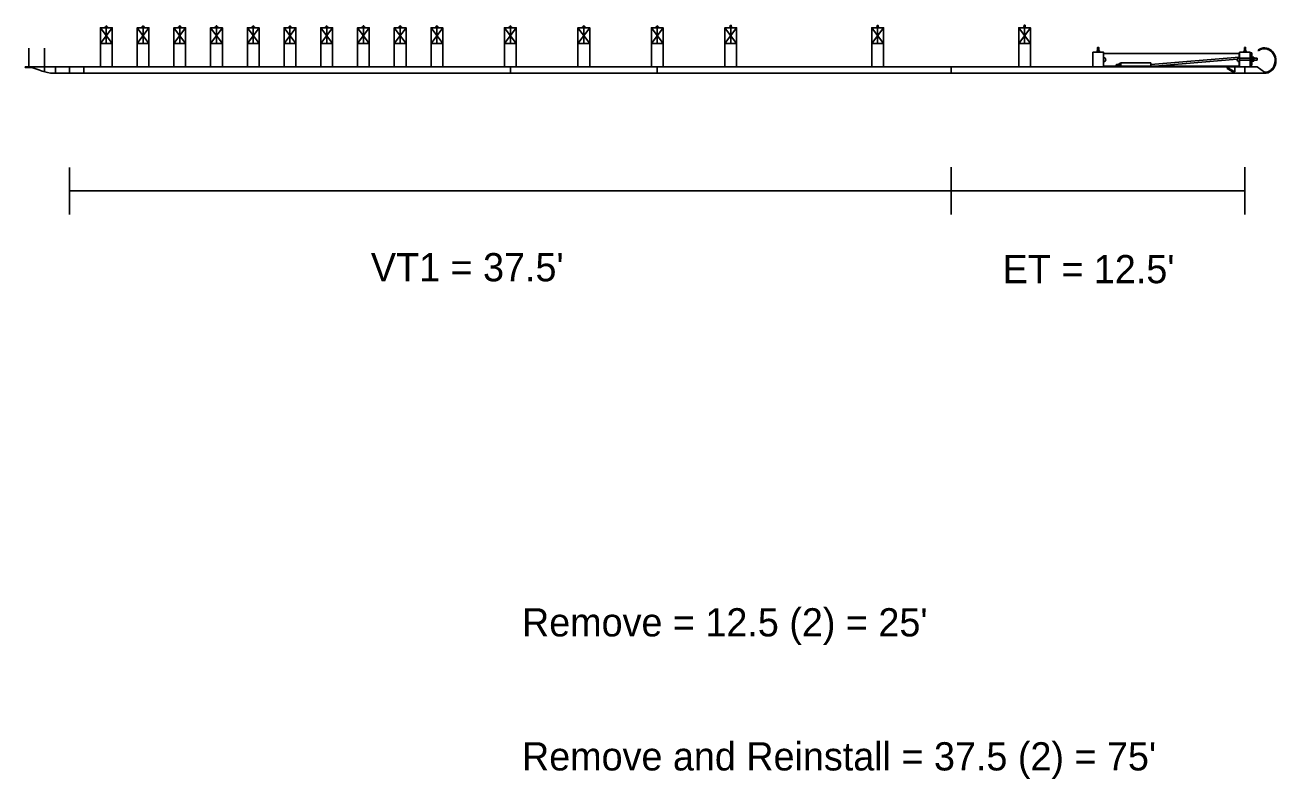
# Model space of a CAD drawing. Extents: x 16537443 to 16538473, y 7054586 to 7055469.
# Drawn here: x 16538142 to 16538195.2, y 7054852.8 to 7054884.9 of the extents above; entities that cross this region are included whole.
import ezdxf

# ---------------------------------------------------------------- set-up
doc = ezdxf.new("R2010")
doc.units = 0
doc.layers.add('Draft_DNC', color=7, linetype='Continuous')

msp = doc.modelspace()

# ---------------------------------------------------------------- linework, layer by layer
at = {"layer": 'Draft_DNC'}
for p, q in [((16538145.683, 7054884.117), (16538145.183, 7054884.784)), ((16538145.183, 7054884.117), (16538145.683, 7054884.784)), ((16538145.683, 7054884.784), (16538145.183, 7054884.784)), ((16538145.353, 7054884.784), (16538145.353, 7054884.801)), ((16538145.513, 7054884.801), (16538145.353, 7054884.801)), ((16538145.393, 7054884.801), (16538145.393, 7054884.838)), ((16538145.473, 7054884.838), (16538145.393, 7054884.838)), ((16538145.409, 7054884.801), (16538145.409, 7054884.838)), ((16538145.423, 7054884.838), (16538145.423, 7054884.867)), ((16538145.443, 7054884.867), (16538145.423, 7054884.867)), ((16538145.433, 7054884.117), (16538145.433, 7054884.784)), ((16538145.443, 7054884.838), (16538145.443, 7054884.867)), ((16538145.457, 7054884.801), (16538145.457, 7054884.838)), ((16538145.473, 7054884.801), (16538145.473, 7054884.838)), ((16538145.513, 7054884.784), (16538145.513, 7054884.801)), ((16538147.246, 7054884.117), (16538146.746, 7054884.784)), ((16538146.746, 7054884.117), (16538147.246, 7054884.784)), ((16538147.246, 7054884.784), (16538146.746, 7054884.784)), ((16538146.916, 7054884.784), (16538146.916, 7054884.801)), ((16538147.076, 7054884.801), (16538146.916, 7054884.801)), ((16538146.956, 7054884.801), (16538146.956, 7054884.838)), ((16538147.036, 7054884.838), (16538146.956, 7054884.838)), ((16538146.972, 7054884.801), (16538146.972, 7054884.838)), ((16538146.986, 7054884.838), (16538146.986, 7054884.867)), ((16538147.006, 7054884.867), (16538146.986, 7054884.867)), ((16538146.996, 7054884.117), (16538146.996, 7054884.784)), ((16538147.006, 7054884.838), (16538147.006, 7054884.867)), ((16538147.02, 7054884.801), (16538147.02, 7054884.838)), ((16538147.036, 7054884.801), (16538147.036, 7054884.838)), ((16538147.076, 7054884.784), (16538147.076, 7054884.801)), ((16538148.808, 7054884.117), (16538148.308, 7054884.784)), ((16538148.308, 7054884.117), (16538148.808, 7054884.784)), ((16538148.808, 7054884.784), (16538148.308, 7054884.784)), ((16538148.478, 7054884.784), (16538148.478, 7054884.801)), ((16538148.638, 7054884.801), (16538148.478, 7054884.801)), ((16538148.518, 7054884.801), (16538148.518, 7054884.838)), ((16538148.598, 7054884.838), (16538148.518, 7054884.838)), ((16538148.534, 7054884.801), (16538148.534, 7054884.838)), ((16538148.548, 7054884.838), (16538148.548, 7054884.867)), ((16538148.568, 7054884.867), (16538148.548, 7054884.867)), ((16538148.558, 7054884.117), (16538148.558, 7054884.784)), ((16538148.568, 7054884.838), (16538148.568, 7054884.867)), ((16538148.582, 7054884.801), (16538148.582, 7054884.838)), ((16538148.598, 7054884.801), (16538148.598, 7054884.838)), ((16538148.638, 7054884.784), (16538148.638, 7054884.801)), ((16538150.371, 7054884.117), (16538149.871, 7054884.784)), ((16538149.871, 7054884.117), (16538150.371, 7054884.784)), ((16538150.371, 7054884.784), (16538149.871, 7054884.784)), ((16538150.041, 7054884.784), (16538150.041, 7054884.801)), ((16538150.201, 7054884.801), (16538150.041, 7054884.801)), ((16538150.081, 7054884.801), (16538150.081, 7054884.838)), ((16538150.161, 7054884.838), (16538150.081, 7054884.838)), ((16538150.097, 7054884.801), (16538150.097, 7054884.838)), ((16538150.111, 7054884.838), (16538150.111, 7054884.867)), ((16538150.131, 7054884.867), (16538150.111, 7054884.867)), ((16538150.121, 7054884.117), (16538150.121, 7054884.784)), ((16538150.131, 7054884.838), (16538150.131, 7054884.867)), ((16538150.145, 7054884.801), (16538150.145, 7054884.838)), ((16538150.161, 7054884.801), (16538150.161, 7054884.838)), ((16538150.201, 7054884.784), (16538150.201, 7054884.801)), ((16538151.933, 7054884.117), (16538151.433, 7054884.784)), ((16538151.433, 7054884.117), (16538151.933, 7054884.784)), ((16538151.933, 7054884.784), (16538151.433, 7054884.784)), ((16538151.603, 7054884.784), (16538151.603, 7054884.801)), ((16538151.763, 7054884.801), (16538151.603, 7054884.801)), ((16538151.643, 7054884.801), (16538151.643, 7054884.838)), ((16538151.723, 7054884.838), (16538151.643, 7054884.838)), ((16538151.659, 7054884.801), (16538151.659, 7054884.838)), ((16538151.673, 7054884.838), (16538151.673, 7054884.867)), ((16538151.693, 7054884.867), (16538151.673, 7054884.867)), ((16538151.683, 7054884.117), (16538151.683, 7054884.784)), ((16538151.693, 7054884.838), (16538151.693, 7054884.867)), ((16538151.707, 7054884.801), (16538151.707, 7054884.838)), ((16538151.723, 7054884.801), (16538151.723, 7054884.838)), ((16538151.763, 7054884.784), (16538151.763, 7054884.801)), ((16538153.496, 7054884.117), (16538152.996, 7054884.784)), ((16538152.996, 7054884.117), (16538153.496, 7054884.784)), ((16538153.496, 7054884.784), (16538152.996, 7054884.784)), ((16538153.166, 7054884.784), (16538153.166, 7054884.801)), ((16538153.326, 7054884.801), (16538153.166, 7054884.801)), ((16538153.206, 7054884.801), (16538153.206, 7054884.838)), ((16538153.286, 7054884.838), (16538153.206, 7054884.838)), ((16538153.222, 7054884.801), (16538153.222, 7054884.838)), ((16538153.236, 7054884.838), (16538153.236, 7054884.867)), ((16538153.256, 7054884.867), (16538153.236, 7054884.867)), ((16538153.246, 7054884.117), (16538153.246, 7054884.784)), ((16538153.256, 7054884.838), (16538153.256, 7054884.867)), ((16538153.27, 7054884.801), (16538153.27, 7054884.838)), ((16538153.286, 7054884.801), (16538153.286, 7054884.838)), ((16538153.326, 7054884.784), (16538153.326, 7054884.801)), ((16538155.058, 7054884.117), (16538154.558, 7054884.784)), ((16538154.558, 7054884.117), (16538155.058, 7054884.784)), ((16538155.058, 7054884.784), (16538154.558, 7054884.784)), ((16538154.728, 7054884.784), (16538154.728, 7054884.801)), ((16538154.888, 7054884.801), (16538154.728, 7054884.801)), ((16538154.768, 7054884.801), (16538154.768, 7054884.838)), ((16538154.848, 7054884.838), (16538154.768, 7054884.838)), ((16538154.784, 7054884.801), (16538154.784, 7054884.838)), ((16538154.798, 7054884.838), (16538154.798, 7054884.867)), ((16538154.818, 7054884.867), (16538154.798, 7054884.867)), ((16538154.808, 7054884.117), (16538154.808, 7054884.784)), ((16538154.818, 7054884.838), (16538154.818, 7054884.867)), ((16538154.832, 7054884.801), (16538154.832, 7054884.838)), ((16538154.848, 7054884.801), (16538154.848, 7054884.838)), ((16538154.888, 7054884.784), (16538154.888, 7054884.801)), ((16538156.621, 7054884.117), (16538156.121, 7054884.784)), ((16538156.121, 7054884.117), (16538156.621, 7054884.784)), ((16538156.621, 7054884.784), (16538156.121, 7054884.784)), ((16538156.291, 7054884.784), (16538156.291, 7054884.801)), ((16538156.451, 7054884.801), (16538156.291, 7054884.801)), ((16538156.331, 7054884.801), (16538156.331, 7054884.838)), ((16538156.411, 7054884.838), (16538156.331, 7054884.838)), ((16538156.347, 7054884.801), (16538156.347, 7054884.838)), ((16538156.361, 7054884.838), (16538156.361, 7054884.867)), ((16538156.381, 7054884.867), (16538156.361, 7054884.867)), ((16538156.371, 7054884.117), (16538156.371, 7054884.784)), ((16538156.381, 7054884.838), (16538156.381, 7054884.867)), ((16538156.395, 7054884.801), (16538156.395, 7054884.838)), ((16538156.411, 7054884.801), (16538156.411, 7054884.838)), ((16538156.451, 7054884.784), (16538156.451, 7054884.801)), ((16538158.183, 7054884.117), (16538157.683, 7054884.784)), ((16538157.683, 7054884.117), (16538158.183, 7054884.784)), ((16538158.183, 7054884.784), (16538157.683, 7054884.784)), ((16538157.853, 7054884.784), (16538157.853, 7054884.801)), ((16538158.013, 7054884.801), (16538157.853, 7054884.801)), ((16538157.893, 7054884.801), (16538157.893, 7054884.838)), ((16538157.973, 7054884.838), (16538157.893, 7054884.838)), ((16538157.909, 7054884.801), (16538157.909, 7054884.838)), ((16538157.923, 7054884.838), (16538157.923, 7054884.867)), ((16538157.943, 7054884.867), (16538157.923, 7054884.867)), ((16538157.933, 7054884.117), (16538157.933, 7054884.784)), ((16538157.943, 7054884.838), (16538157.943, 7054884.867)), ((16538157.957, 7054884.801), (16538157.957, 7054884.838)), ((16538157.973, 7054884.801), (16538157.973, 7054884.838)), ((16538158.013, 7054884.784), (16538158.013, 7054884.801)), ((16538159.746, 7054884.117), (16538159.246, 7054884.784)), ((16538159.246, 7054884.117), (16538159.746, 7054884.784)), ((16538159.746, 7054884.784), (16538159.246, 7054884.784)), ((16538159.416, 7054884.784), (16538159.416, 7054884.801)), ((16538159.576, 7054884.801), (16538159.416, 7054884.801)), ((16538159.456, 7054884.801), (16538159.456, 7054884.838)), ((16538159.536, 7054884.838), (16538159.456, 7054884.838)), ((16538159.472, 7054884.801), (16538159.472, 7054884.838)), ((16538159.486, 7054884.838), (16538159.486, 7054884.867)), ((16538159.506, 7054884.867), (16538159.486, 7054884.867)), ((16538159.496, 7054884.117), (16538159.496, 7054884.784)), ((16538159.506, 7054884.838), (16538159.506, 7054884.867)), ((16538159.52, 7054884.801), (16538159.52, 7054884.838)), ((16538159.536, 7054884.801), (16538159.536, 7054884.838)), ((16538159.576, 7054884.784), (16538159.576, 7054884.801)), ((16538162.871, 7054884.117), (16538162.371, 7054884.784)), ((16538162.371, 7054884.117), (16538162.871, 7054884.784)), ((16538162.871, 7054884.784), (16538162.371, 7054884.784)), ((16538162.541, 7054884.784), (16538162.541, 7054884.801)), ((16538162.701, 7054884.801), (16538162.541, 7054884.801)), ((16538162.581, 7054884.801), (16538162.581, 7054884.838)), ((16538162.661, 7054884.838), (16538162.581, 7054884.838)), ((16538162.597, 7054884.801), (16538162.597, 7054884.838)), ((16538162.611, 7054884.838), (16538162.611, 7054884.867)), ((16538162.631, 7054884.867), (16538162.611, 7054884.867)), ((16538162.621, 7054884.117), (16538162.621, 7054884.784)), ((16538162.631, 7054884.838), (16538162.631, 7054884.867)), ((16538162.645, 7054884.801), (16538162.645, 7054884.838)), ((16538162.661, 7054884.801), (16538162.661, 7054884.838)), ((16538162.701, 7054884.784), (16538162.701, 7054884.801)), ((16538165.996, 7054884.117), (16538165.496, 7054884.784)), ((16538165.496, 7054884.117), (16538165.996, 7054884.784)), ((16538165.996, 7054884.784), (16538165.496, 7054884.784)), ((16538165.666, 7054884.784), (16538165.666, 7054884.801)), ((16538165.826, 7054884.801), (16538165.666, 7054884.801)), ((16538165.706, 7054884.801), (16538165.706, 7054884.838)), ((16538165.786, 7054884.838), (16538165.706, 7054884.838)), ((16538165.722, 7054884.801), (16538165.722, 7054884.838)), ((16538165.736, 7054884.838), (16538165.736, 7054884.867)), ((16538165.756, 7054884.867), (16538165.736, 7054884.867)), ((16538165.746, 7054884.117), (16538165.746, 7054884.784)), ((16538165.756, 7054884.838), (16538165.756, 7054884.867)), ((16538165.77, 7054884.801), (16538165.77, 7054884.838)), ((16538165.786, 7054884.801), (16538165.786, 7054884.838)), ((16538165.826, 7054884.784), (16538165.826, 7054884.801)), ((16538169.121, 7054884.117), (16538168.621, 7054884.784)), ((16538168.621, 7054884.117), (16538169.121, 7054884.784)), ((16538169.121, 7054884.784), (16538168.621, 7054884.784)), ((16538168.791, 7054884.784), (16538168.791, 7054884.801)), ((16538168.951, 7054884.801), (16538168.791, 7054884.801)), ((16538168.831, 7054884.801), (16538168.831, 7054884.838)), ((16538168.911, 7054884.838), (16538168.831, 7054884.838)), ((16538168.847, 7054884.801), (16538168.847, 7054884.838)), ((16538168.861, 7054884.838), (16538168.861, 7054884.867)), ((16538168.881, 7054884.867), (16538168.861, 7054884.867)), ((16538168.871, 7054884.117), (16538168.871, 7054884.784)), ((16538168.881, 7054884.838), (16538168.881, 7054884.867)), ((16538168.895, 7054884.801), (16538168.895, 7054884.838)), ((16538168.911, 7054884.801), (16538168.911, 7054884.838)), ((16538168.951, 7054884.784), (16538168.951, 7054884.801)), ((16538171.746, 7054884.785), (16538172.246, 7054884.119)), ((16538172.246, 7054884.785), (16538171.746, 7054884.119)), ((16538171.996, 7054884.883), (16538171.996, 7054884.89)), ((16538171.996, 7054884.119), (16538171.996, 7054884.785)), ((16538177.996, 7054884.785), (16538178.496, 7054884.119)), ((16538178.496, 7054884.785), (16538177.996, 7054884.119)), ((16538178.246, 7054884.883), (16538178.246, 7054884.89)), ((16538178.246, 7054884.119), (16538178.246, 7054884.785)), ((16538184.246, 7054884.118), (16538184.746, 7054884.785)), ((16538184.246, 7054884.785), (16538184.746, 7054884.118)), ((16538184.496, 7054884.892), (16538184.496, 7054884.899)), ((16538184.496, 7054884.785), (16538184.496, 7054884.118)), ((16538142.142, 7054883.909), (16538142.142, 7054883.091)), ((16538142.808, 7054883.909), (16538142.808, 7054882.907)), ((16538145.184, 7054884.117), (16538145.683, 7054884.117)), ((16538145.184, 7054883.118), (16538145.184, 7054884.117)), ((16538145.683, 7054884.117), (16538145.683, 7054883.118)), ((16538146.746, 7054884.117), (16538147.246, 7054884.117)), ((16538146.746, 7054883.118), (16538146.746, 7054884.117)), ((16538147.246, 7054884.117), (16538147.246, 7054883.118)), ((16538148.309, 7054884.117), (16538148.808, 7054884.117)), ((16538148.309, 7054883.118), (16538148.309, 7054884.117)), ((16538148.808, 7054884.117), (16538148.808, 7054883.118)), ((16538149.871, 7054884.117), (16538150.371, 7054884.117)), ((16538149.871, 7054883.118), (16538149.871, 7054884.117)), ((16538150.371, 7054884.117), (16538150.371, 7054883.118)), ((16538151.434, 7054884.117), (16538151.933, 7054884.117)), ((16538151.434, 7054883.118), (16538151.434, 7054884.117)), ((16538151.933, 7054884.117), (16538151.933, 7054883.118)), ((16538152.996, 7054884.117), (16538153.496, 7054884.117)), ((16538152.996, 7054883.118), (16538152.996, 7054884.117)), ((16538153.496, 7054884.117), (16538153.496, 7054883.118)), ((16538154.559, 7054884.117), (16538155.058, 7054884.117)), ((16538154.559, 7054883.118), (16538154.559, 7054884.117)), ((16538155.058, 7054884.117), (16538155.058, 7054883.118)), ((16538156.121, 7054884.117), (16538156.621, 7054884.117)), ((16538156.121, 7054883.118), (16538156.121, 7054884.117)), ((16538156.121, 7054884.117), (16538156.621, 7054884.117)), ((16538156.121, 7054883.118), (16538156.121, 7054884.117)), ((16538156.621, 7054884.117), (16538156.621, 7054883.118)), ((16538156.621, 7054884.117), (16538156.621, 7054883.118)), ((16538157.684, 7054884.117), (16538158.183, 7054884.117)), ((16538157.684, 7054883.118), (16538157.684, 7054884.117)), ((16538158.183, 7054884.117), (16538158.183, 7054883.118)), ((16538159.246, 7054884.117), (16538159.746, 7054884.117)), ((16538159.246, 7054883.118), (16538159.246, 7054884.117)), ((16538159.746, 7054884.117), (16538159.746, 7054883.118)), ((16538162.371, 7054884.117), (16538162.871, 7054884.117)), ((16538162.371, 7054883.118), (16538162.371, 7054884.117)), ((16538162.871, 7054884.117), (16538162.871, 7054883.118)), ((16538165.496, 7054884.117), (16538165.996, 7054884.117)), ((16538165.496, 7054883.118), (16538165.496, 7054884.117)), ((16538165.996, 7054884.117), (16538165.996, 7054883.118)), ((16538168.621, 7054884.117), (16538169.121, 7054884.117)), ((16538168.621, 7054883.118), (16538168.621, 7054884.117)), ((16538169.121, 7054884.117), (16538169.121, 7054883.118)), ((16538171.746, 7054884.119), (16538172.246, 7054884.119)), ((16538171.746, 7054883.118), (16538171.746, 7054884.119)), ((16538172.246, 7054884.119), (16538172.246, 7054883.118)), ((16538177.996, 7054884.119), (16538178.496, 7054884.119)), ((16538177.996, 7054883.118), (16538177.996, 7054884.119)), ((16538178.496, 7054884.119), (16538178.496, 7054883.118)), ((16538194.429, 7054883.837), (16538194.447, 7054883.807)), ((16538141.975, 7054883.118), (16538141.975, 7054883.092)), ((16538141.975, 7054883.118), (16538181.371, 7054883.118)), ((16538143.267, 7054882.847), (16538143.267, 7054883.118)), ((16538143.871, 7054882.847), (16538143.871, 7054883.118)), ((16538144.475, 7054882.847), (16538144.475, 7054883.118)), ((16538145.683, 7054883.118), (16538145.184, 7054883.118)), ((16538147.246, 7054883.118), (16538146.746, 7054883.118)), ((16538148.808, 7054883.118), (16538148.309, 7054883.118)), ((16538150.371, 7054883.118), (16538149.871, 7054883.118)), ((16538151.933, 7054883.118), (16538151.434, 7054883.118)), ((16538153.496, 7054883.118), (16538152.996, 7054883.118)), ((16538155.058, 7054883.118), (16538154.559, 7054883.118)), ((16538156.621, 7054883.118), (16538156.121, 7054883.118)), ((16538156.621, 7054883.118), (16538156.121, 7054883.118)), ((16538158.183, 7054883.118), (16538157.684, 7054883.118)), ((16538159.746, 7054883.118), (16538159.246, 7054883.118)), ((16538162.871, 7054883.118), (16538162.371, 7054883.118)), ((16538162.621, 7054882.847), (16538162.621, 7054883.118)), ((16538165.996, 7054883.118), (16538165.496, 7054883.118)), ((16538169.121, 7054883.118), (16538168.621, 7054883.118)), ((16538168.871, 7054882.847), (16538168.871, 7054883.118)), ((16538172.246, 7054883.118), (16538171.746, 7054883.118)), ((16538178.496, 7054883.118), (16538177.996, 7054883.118)), ((16538181.371, 7054882.847), (16538181.371, 7054883.118)), ((16538193.871, 7054883.118), (16538181.371, 7054883.118)), ((16538181.371, 7054883.118), (16538181.371, 7054882.847)), ((16538188.402, 7054883.137), (16538188.402, 7054883.217)), ((16538188.413, 7054883.15), (16538188.413, 7054883.204)), ((16538188.425, 7054883.137), (16538188.425, 7054883.217)), ((16538188.437, 7054883.15), (16538188.437, 7054883.204)), ((16538188.449, 7054883.137), (16538188.449, 7054883.217)), ((16538188.461, 7054883.15), (16538188.461, 7054883.204)), ((16538188.473, 7054883.137), (16538188.473, 7054883.217)), ((16538188.554, 7054883.206), (16538188.487, 7054883.206)), ((16538193.632, 7054883.532), (16538189.861, 7054883.216)), ((16538193.545, 7054883.448), (16538189.861, 7054883.136)), ((16538194.11, 7054883.486), (16538193.632, 7054883.486)), ((16538194.11, 7054883.41), (16538193.632, 7054883.41)), ((16538193.871, 7054883.118), (16538193.871, 7054882.847)), ((16538194.18, 7054883.492), (16538194.245, 7054883.492)), ((16538194.18, 7054883.409), (16538194.245, 7054883.409)), ((16538142.225, 7054883.092), (16538141.975, 7054883.092)), ((16538142.708, 7054882.94), (16538142.565, 7054882.996)), ((16538143.17, 7054882.847), (16538181.371, 7054882.847)), ((16538143.267, 7054882.847), (16538168.871, 7054882.848)), ((16538181.371, 7054882.847), (16538193.871, 7054882.847)), ((16538143.871, 7054877.847), (16538143.871, 7054878.847)), ((16538181.371, 7054877.848), (16538181.371, 7054878.848)), ((16538193.871, 7054877.848), (16538193.871, 7054878.848)), ((16538143.871, 7054877.847), (16538181.371, 7054877.848)), ((16538143.871, 7054876.847), (16538143.871, 7054877.847)), ((16538181.371, 7054877.848), (16538193.871, 7054877.848)), ((16538181.371, 7054876.848), (16538181.371, 7054877.848)), ((16538193.871, 7054876.848), (16538193.871, 7054877.848))]:
    msp.add_line(p, q, dxfattribs=at)
for points in [[(16538145.183, 7054884.117), (16538145.683, 7054884.117), (16538145.683, 7054884.784), (16538145.183, 7054884.784)], [(16538146.746, 7054884.117), (16538147.246, 7054884.117), (16538147.246, 7054884.784), (16538146.746, 7054884.784)], [(16538148.308, 7054884.117), (16538148.808, 7054884.117), (16538148.808, 7054884.784), (16538148.308, 7054884.784)], [(16538149.871, 7054884.117), (16538150.371, 7054884.117), (16538150.371, 7054884.784), (16538149.871, 7054884.784)], [(16538151.433, 7054884.117), (16538151.933, 7054884.117), (16538151.933, 7054884.784), (16538151.433, 7054884.784)], [(16538152.996, 7054884.117), (16538153.496, 7054884.117), (16538153.496, 7054884.784), (16538152.996, 7054884.784)], [(16538154.558, 7054884.117), (16538155.058, 7054884.117), (16538155.058, 7054884.784), (16538154.558, 7054884.784)], [(16538156.121, 7054884.117), (16538156.621, 7054884.117), (16538156.621, 7054884.784), (16538156.121, 7054884.784)], [(16538157.683, 7054884.117), (16538158.183, 7054884.117), (16538158.183, 7054884.784), (16538157.683, 7054884.784)], [(16538159.246, 7054884.117), (16538159.746, 7054884.117), (16538159.746, 7054884.784), (16538159.246, 7054884.784)], [(16538162.371, 7054884.117), (16538162.871, 7054884.117), (16538162.871, 7054884.784), (16538162.371, 7054884.784)], [(16538165.496, 7054884.117), (16538165.996, 7054884.117), (16538165.996, 7054884.784), (16538165.496, 7054884.784)], [(16538168.621, 7054884.117), (16538169.121, 7054884.117), (16538169.121, 7054884.784), (16538168.621, 7054884.784)], [(16538171.746, 7054884.119), (16538172.246, 7054884.119), (16538172.246, 7054884.785), (16538171.746, 7054884.785)], [(16538177.996, 7054884.119), (16538178.496, 7054884.119), (16538178.496, 7054884.785), (16538177.996, 7054884.785)], [(16538184.246, 7054884.118), (16538184.746, 7054884.118), (16538184.746, 7054884.785), (16538184.246, 7054884.785)], [(16538184.246, 7054884.118), (16538184.746, 7054884.118), (16538184.746, 7054883.118), (16538184.246, 7054883.118)], [(16538187.402, 7054883.745), (16538187.86, 7054883.745), (16538187.86, 7054883.12), (16538187.402, 7054883.12)], [(16538187.578, 7054883.746), (16538187.578, 7054883.806), (16538187.678, 7054883.806), (16538187.678, 7054883.746)], [(16538187.603, 7054883.806), (16538187.603, 7054883.947), (16538187.653, 7054883.95), (16538187.653, 7054883.806)], [(16538193.642, 7054883.745), (16538194.1, 7054883.745), (16538194.1, 7054883.12), (16538193.642, 7054883.12)], [(16538193.821, 7054883.807), (16538193.921, 7054883.807), (16538193.921, 7054883.747), (16538193.821, 7054883.747)], [(16538193.846, 7054883.948), (16538193.896, 7054883.952), (16538193.896, 7054883.807), (16538193.846, 7054883.807)], [(16538194.11, 7054883.713), (16538194.16, 7054883.713), (16538194.16, 7054883.187), (16538194.11, 7054883.187)], [(16538194.16, 7054883.56), (16538194.172, 7054883.56), (16538194.172, 7054883.341), (16538194.16, 7054883.341)], [(16538194.18, 7054883.533), (16538194.245, 7054883.533), (16538194.253, 7054883.522), (16538194.253, 7054883.379), (16538194.245, 7054883.368), (16538194.18, 7054883.368), (16538194.172, 7054883.379), (16538194.172, 7054883.522)], [(16538194.39, 7054883.494), (16538194.39, 7054883.407), (16538194.253, 7054883.407), (16538194.253, 7054883.494)]]:
    msp.add_lwpolyline(points, close=True, dxfattribs=at)
for points in [[(16538171.962, 7054884.785), (16538171.962, 7054884.828), (16538172.029, 7054884.828), (16538172.029, 7054884.785)], [(16538171.976, 7054884.828), (16538171.976, 7054884.883), (16538172.015, 7054884.883), (16538172.015, 7054884.828)], [(16538178.212, 7054884.785), (16538178.212, 7054884.828), (16538178.279, 7054884.828), (16538178.279, 7054884.785)], [(16538178.226, 7054884.828), (16538178.226, 7054884.883), (16538178.265, 7054884.883), (16538178.265, 7054884.828)], [(16538184.462, 7054884.785), (16538184.462, 7054884.832), (16538184.529, 7054884.832), (16538184.529, 7054884.785)], [(16538184.476, 7054884.832), (16538184.476, 7054884.892), (16538184.515, 7054884.892), (16538184.515, 7054884.832)], [(16538187.86, 7054883.515), (16538187.86, 7054883.693), (16538193.632, 7054883.693), (16538193.632, 7054883.512)], [(16538193.632, 7054883.332), (16538193.632, 7054883.154), (16538187.86, 7054883.154), (16538187.86, 7054883.335)], [(16538188.389, 7054883.15), (16538188.39, 7054883.204), (16538188.402, 7054883.217), (16538188.487, 7054883.217)], [(16538188.555, 7054883.239), (16538188.487, 7054883.239), (16538188.487, 7054883.129)], [(16538188.586, 7054883.283), (16538188.555, 7054883.283), (16538188.554, 7054883.129)], [(16538189.861, 7054883.128), (16538189.861, 7054883.287), (16538188.586, 7054883.287), (16538188.586, 7054883.283), (16538188.585, 7054883.129)], [(16538194.701, 7054882.891), (16538194.392, 7054883.118), (16538193.445, 7054883.118), (16538193.445, 7054882.925)], [(16538193.423, 7054882.912), (16538193.136, 7054883.094), (16538193.116, 7054883.056), (16538193.445, 7054882.847), (16538194.701, 7054882.847)]]:
    msp.add_lwpolyline(points, dxfattribs=at)
for centre, start, end in [((16538187.86, 7054883.425), 269.97, 89.97), ((16538193.632, 7054883.422), 89.97, 270.03)]:
    msp.add_arc(centre, 0.0903, start, end, dxfattribs=at)
for centre, major_axis, ratio, start_param, end_param in [((16538194.701, 7054883.387), (0, -0.54), 0.909091, 6.282661, 10.012044), ((16538194.701, 7054883.391), (0, 0.501), 0.909091, 3.141069, 6.875265), ((16538194.204, 7054883.509), (0, -0.0349), 0.909091, 3.983294, 4.635297), ((16538194.201, 7054883.514), (0, -0.032), 0.909091, 4.75885, 5.47213), ((16538194.274, 7054883.448), (0, -0.112), 0.909091, 4.313584, 4.691037), ((16538194.274, 7054883.453), (0, -0.112), 0.909091, 4.733424, 5.111511), ((16538194.204, 7054883.386), (0, -0.0349), 0.909091, 3.983285, 4.635291), ((16538194.201, 7054883.39), (0, -0.032), 0.909091, 4.758859, 5.472106), ((16538194.221, 7054883.509), (0, 0.0349), 0.909091, 4.789481, 5.441484), ((16538194.224, 7054883.514), (0, 0.032), 0.909091, 3.952648, 4.665928), ((16538194.151, 7054883.448), (0, 0.112), 0.909091, 4.733741, 5.111194), ((16538194.151, 7054883.453), (0, 0.112), 0.909091, 4.313267, 4.691354), ((16538194.221, 7054883.386), (0, 0.0349), 0.909091, 4.789487, 5.441493), ((16538194.224, 7054883.39), (0, 0.032), 0.909091, 3.952672, 4.665919), ((16538142.013, 7054881.769), (-1.379, 0), 0.97085, 4.300427, 4.558114), ((16538143.25, 7054884.342), (1.542, 0), 0.97085, 4.353641, 4.660842), ((16538193.43, 7054882.925), (0, 0.0161), 0.909091, 2.617197, 4.711868)]:
    msp.add_ellipse(centre, major_axis=major_axis, ratio=ratio, start_param=start_param, end_param=end_param, dxfattribs=at)

# ---------------------------------------------------------------- texts
for s, p in [("VT1 = 37.5'", (16538156.688, 7054874.001)), ("ET = 12.5'", (16538183.565, 7054873.92)), ("Remove = 12.5 (2) = 25'", (16538163.116, 7054858.898)), ("Remove and Reinstall = 37.5 (2) = 75'", (16538163.116, 7054853.198))]:
    msp.add_text(s, height=1.2, rotation=0.001, dxfattribs=at).set_placement(p)

doc.saveas('drawing.dxf')
